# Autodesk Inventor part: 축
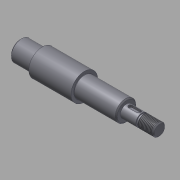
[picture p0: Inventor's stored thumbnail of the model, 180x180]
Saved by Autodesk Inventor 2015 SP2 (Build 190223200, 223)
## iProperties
Created: 2015-12
Part Number: 축
Material: 강철, 연강
Document SubType Name: Modeling
Designer: mdu
Density: 7.86 g/cm^3
Appearance: 강철
CustomPartVersion: 1
Author: mdu
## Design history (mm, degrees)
sketch "스케치5"
  geometry: L1 (0, 0)-(135, 0); L2 (0, 0)-(135, 0); L3 (135, 0)-(135, 6); L4 (103, 6)-(103, 10); L5 (103, 10)-(62, 10); L6 (62, 10)-(62, 13); L7 (62, 13)-(21, 13); L8 (21, 13)-(21, 10); L9 (21, 10)-(0, 10); L10 (0, 10)-(0, 0); L11 (118, 6)-(118, 5); L12 (118, 5)-(120, 5); L13 (120, 5)-(120, 6); L14 (135, 6)-(120, 6); L15 (118, 6)-(103, 6)
  constraints: 31 end point, 12 perpendicular, 9 parallel, 1 collinear, 1 horizontal
  dimensions: "d43" = 20 diameter of L9 L1; "d44" = 26 diameter of L7 L1; "d45" = 20 diameter of L5 L2; "d47" = 41 distance of L6.end L7.end; "d48" = 32 distance between parallel lines of L3 L4; "d50" = 21 distance of L8.end L9.end; "d52" = 12 diameter of L14 L1; "d53" = 15 distance between parallel lines of L3 L13; "d54" = 2 distance of L11.end L12.end; "d55" = 1 distance between parallel lines of L14 L12; "d64" = 135 distance of L1.start L1.end
revolve "회전4" sketch "스케치5" stored, may be unused: angle "d51" = 90 deg
feature "스레드6" dims "d56" = 10, "d57" = 0
chamfer "모따기6" distance "d32" = 1; stored, may be unused: second distance "d33" = 0.4, angle "d34" = 45 deg
chamfer "모따기5" distance "d27" = 1; stored, may be unused: second distance "d28" = 0.125, angle "d29" = 45 deg
fillet "모깎기1" dims "d17" = 0.3
fillet "모깎기2" dims "d18" = 0.3
chamfer "모따기3" distance "d19" = 1; stored, may be unused: second distance "d20" = 1, angle "d21" = 45 deg
node "작업 평면1"
sketch "스케치6"
  geometry: L1 (-3.5, 2)-(4.5, 2); L2 (4.5, -2)-(-3.5, -2); L3 (-7.5, 9)-(-7.5, -9) reference; A1 r 2 centre (4.5, 0) between (4.5, -2) and (4.5, 2); A2 r 2 centre (-3.5, 0) between (-3.5, 2) and (-3.5, -2); 1 further point
  constraints: 4 end point, 4 point on circle, 4 tangent, 2 centre point, 1 horizontal, 1 horizontal alignment, 1 parallel
  dimensions: "d59" = 2 distance edge to line of A2 L3; "d60" = 12 dimension on A1 A2; "d61" = 4 distance between parallel lines of L2 L1
extrude "돌출1" cut sketch "스케치6" distance "d62" = 2.3; taper "d63" = 0 deg
node "솔리드1"
node "솔리드2"
other parameters: "d46" = 12
